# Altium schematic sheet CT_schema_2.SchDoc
size 271 x 273 mm
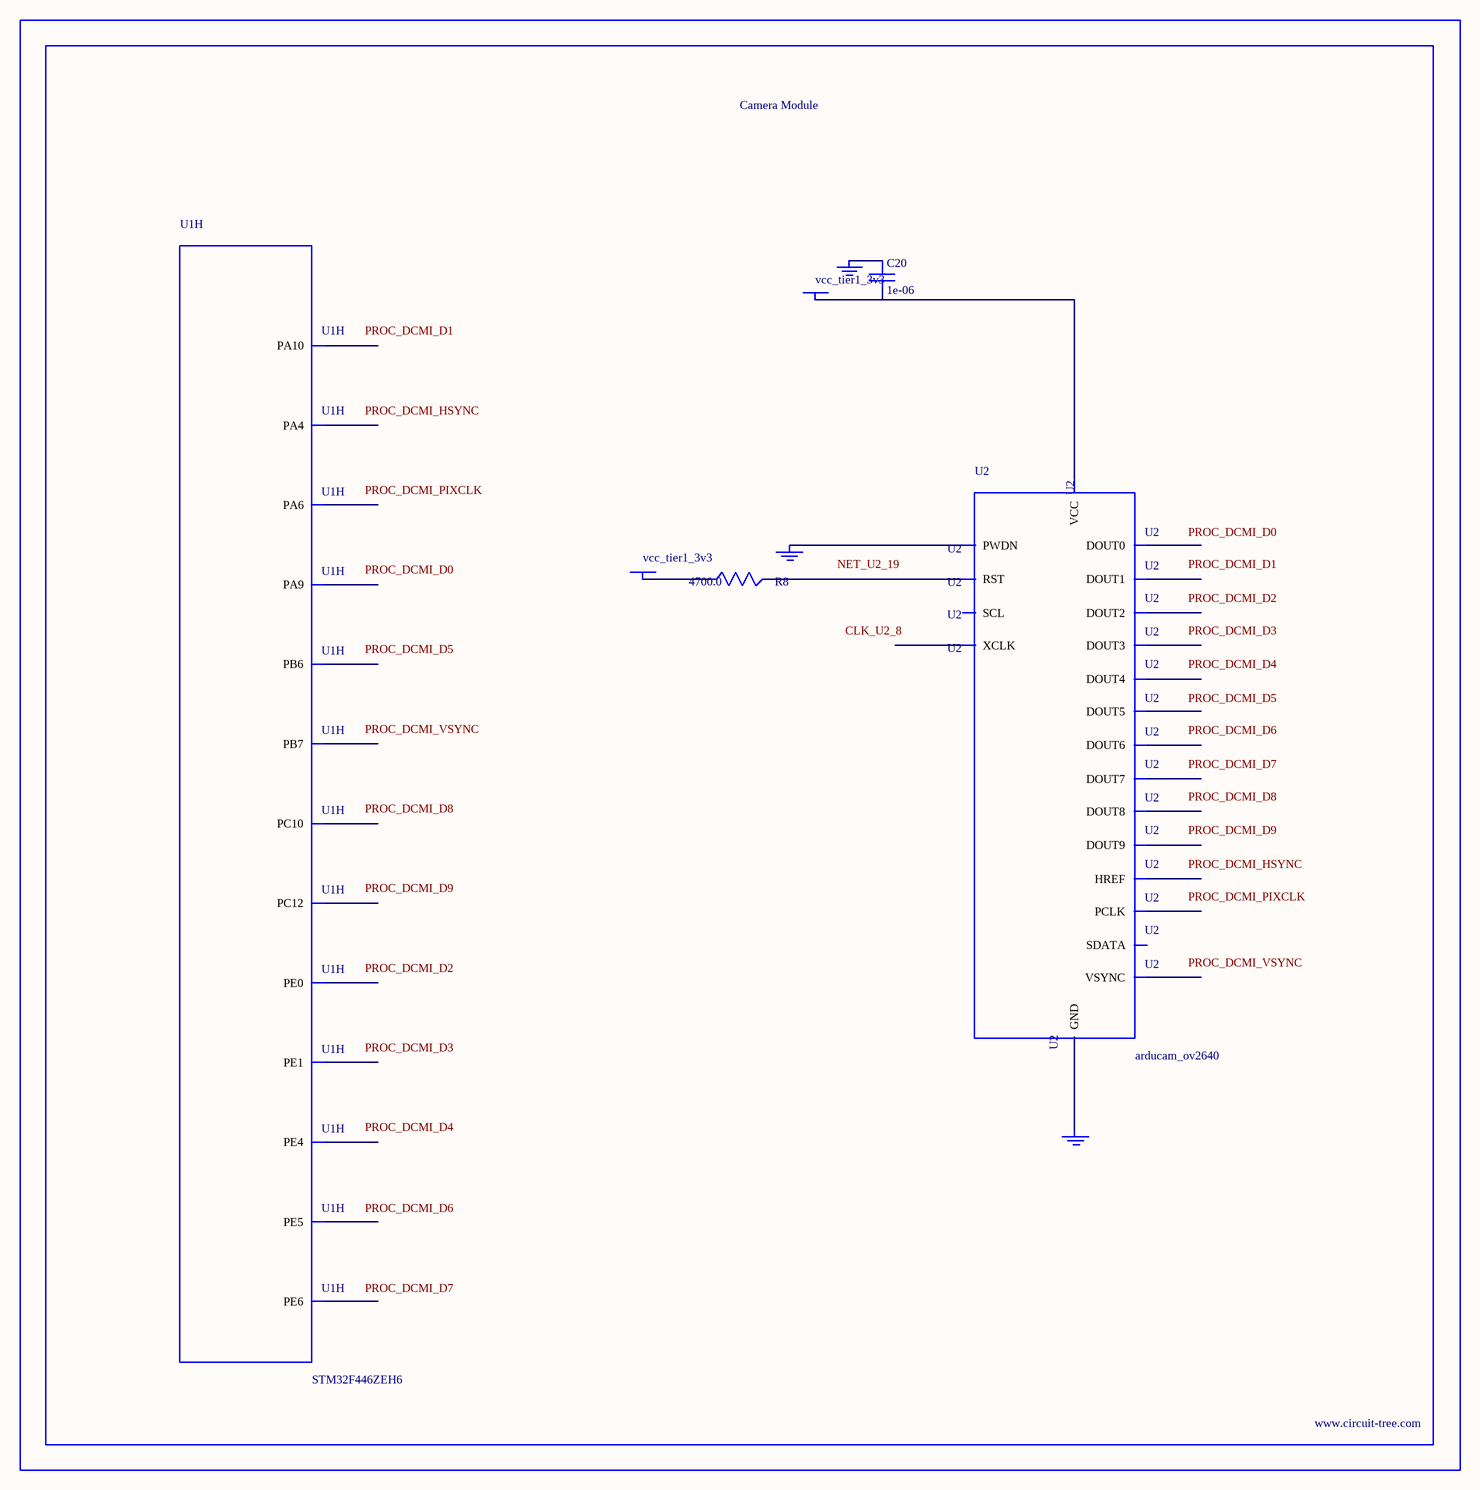
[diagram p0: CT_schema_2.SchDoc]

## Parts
BORDER1  (no value)
C20  1e-06  [C0603]
GND_INSTANCE_1_0  (no value)
GND_INSTANCE_1_1  (no value)
GND_INSTANCE_1_2  (no value)
POWER_INSTANCE_1_0  vcc_tier1_3v3
POWER_INSTANCE_1_1  vcc_tier1_3v3
R8  4700.0  [R0603]
U1  STM32F446ZEH6  [UFBGA144]  (part H of 10)
U2  arducam_ov2640  [ARDUCAM]

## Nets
NetC20_1: C20.1 GND_INSTANCE_1_0.0(GND)
NetC20_2: C20.2 POWER_INSTANCE_1_0.0(PWR) U2.1(VCC)
NetGND_INSTANCE_1_1_0: GND_INSTANCE_1_1.0(GND) U2.20(PWDN)
NetGND_INSTANCE_1_2_0: GND_INSTANCE_1_2.0(GND) U2.2(GND)
NetPOWER_INSTANCE_1_1_0: POWER_INSTANCE_1_1.0(PWR) R8.1
NetR8_2: R8.2 U2.19(RST)

Not connected (* = marked no-connect by the designer): U1 A4(PE1) A5(PE0) B2(PE4) B3(PE5) B4(PE6) B11(PC10) C6(PB6) C10(PC12) D6(PB7) D11(PA10) D12(PA9) J3(PA4) L3(PA6); U2 3(SCL) 4(SDATA) 5(VSYNC) 6(HREF) 7(PCLK) 8(XCLK) 9(DOUT9) 10(DOUT8) 11(DOUT7) 12(DOUT6) 13(DOUT5) 14(DOUT4) 15(DOUT3) 16(DOUT2) 17(DOUT1) 18(DOUT0)

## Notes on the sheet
- Labels drawn without touching a wire or pin: CLK_U2_8, NET_U2_19, PROC_DCMI_D0, PROC_DCMI_D1, PROC_DCMI_D2, PROC_DCMI_D3, PROC_DCMI_D4, PROC_DCMI_D5, PROC_DCMI_D6, PROC_DCMI_D7, PROC_DCMI_D8, PROC_DCMI_D9, PROC_DCMI_HSYNC, PROC_DCMI_PIXCLK, PROC_DCMI_VSYNC

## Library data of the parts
BORDER1 = BORDER_PAGE1
C20 = C0603C105K3RACTU
GND_INSTANCE_1_0-GND_INSTANCE_1_2 = GND
POWER_INSTANCE_1_0 POWER_INSTANCE_1_1 = PWR
R8 = RC0603JR-074K7L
